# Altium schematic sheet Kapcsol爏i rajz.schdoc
size 319 x 215 mm
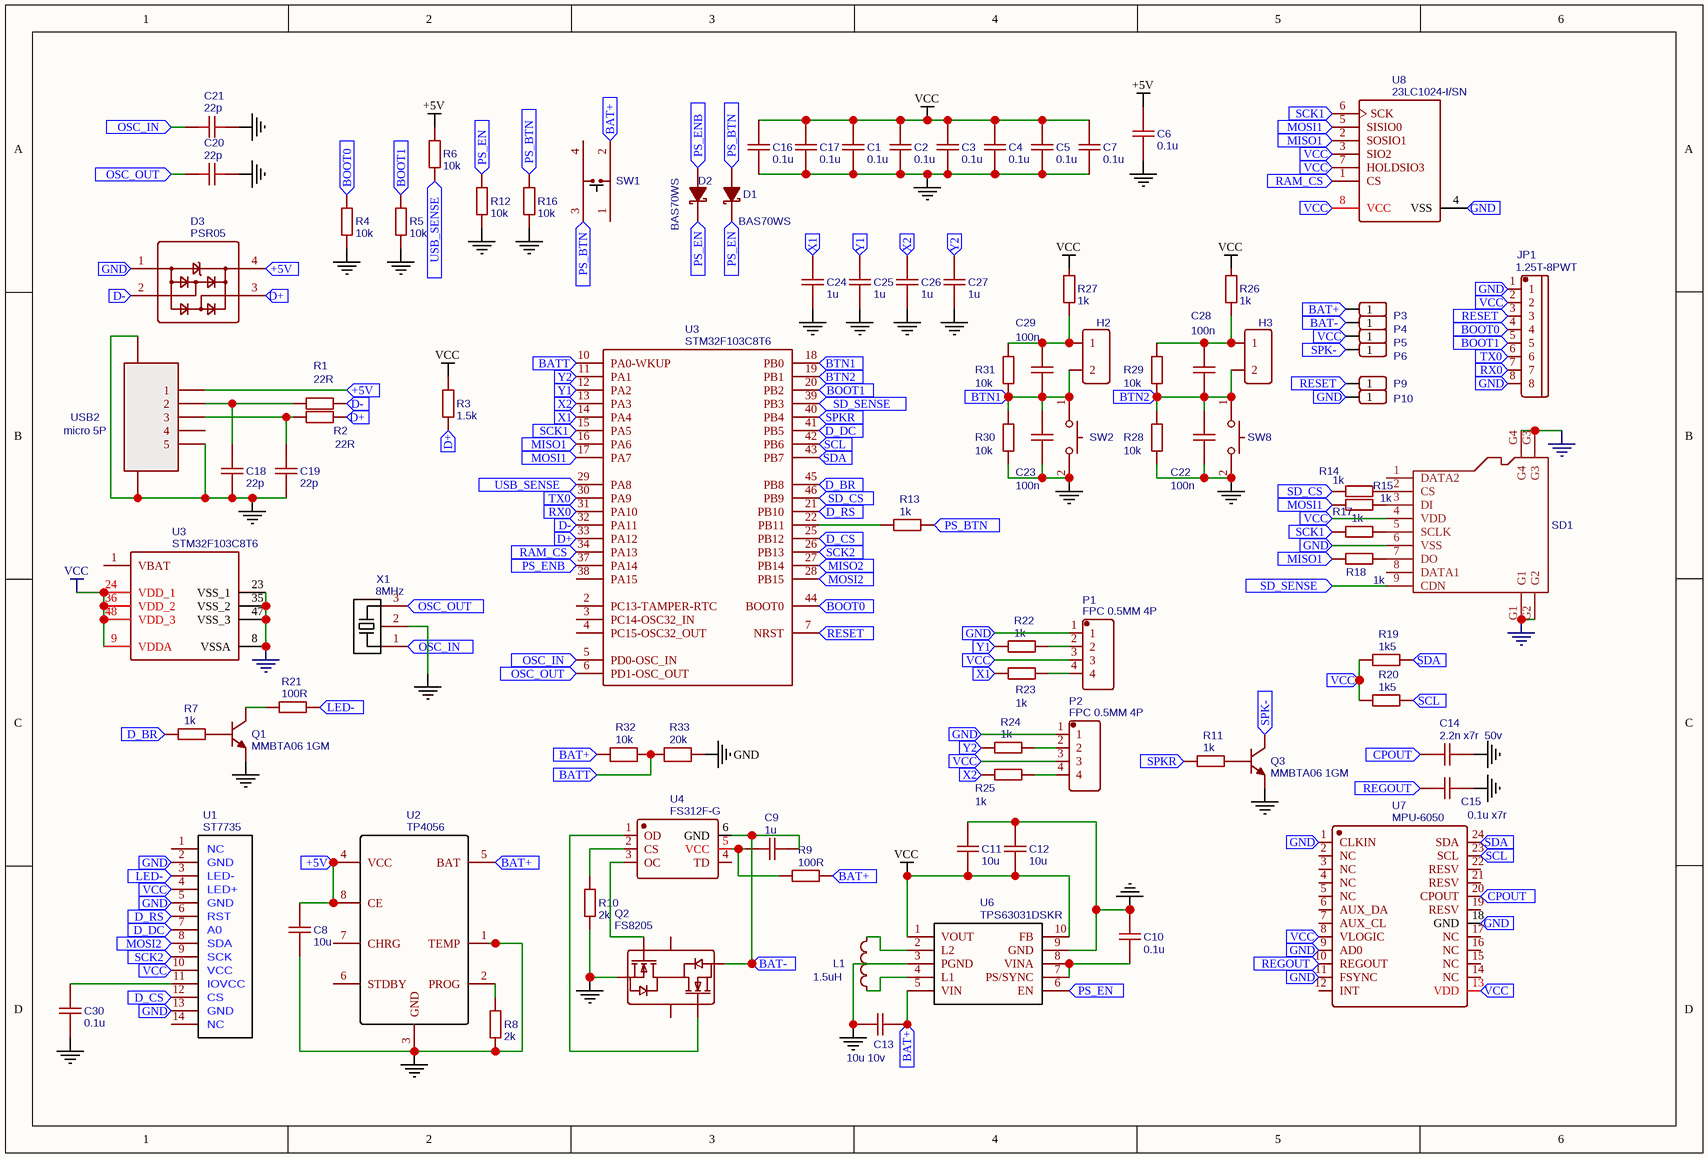
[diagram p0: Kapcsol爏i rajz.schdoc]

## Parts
(Parts that share a designator on the sheet are numbered #1, #2 ... from top to bottom, then left to right.)
C1  0.1u  [0805]
C2  0.1u  [0805]
C3  0.1u  [0805]
C4  0.1u  [0805]
C5  0.1u  [0805]
C6  0.1u  [0805]
C7  0.1u  [0805]
C8  10u  [0805]
C9  1u  [0805]
C10  0.1u  [0805]
C11  10u  [0805]
C12  10u  [0805]
C13  10u 10v  [0805]
C14  2.2n x7r  50v  [0805]
C15  0.1u x7r  [0805]
C16  0.1u  [0805]
C17  0.1u  [0805]
C18  22p  [0805]
C19  22p  [0805]
C20  22p  [0805]
C21  22p  [0805]
C22  100n  [0805]
C23  100n  [0805]
C24  1u  [0805]
C25  1u  [0805]
C26  1u  [0805]
C27  1u  [0805]
C28  100n  [0805]
C29  100n  [0805]
C30  0.1u  [0805]
D1  BAS70WS  [SOD-323]
D2  BAS70WS  [SOD-323]
D3  PSR05  [SOT-143]
H2  Header-Male-2.54_1x2  [HDR-2X1/2.54]  (value not drawn)
H3  Header-Male-2.54_1x2  [HDR-2X1/2.54]  (value not drawn)
JP1  1.25T-8PWT  [1.25T-8PWT]
L1  1.5uH  [3.0*3.0*1.5MM]
P1  FPC 0.5MM 4P  [FPC-0.5MM-LSSJ-H2.0-4P]
P2  FPC 0.5MM 4P  [FPC-0.5MM-LSSJ-H2.0-4P]
P3  Header-Male-2.54_1x1  [HDR-1X1/2.54]  (value not drawn)
P4  Header-Male-2.54_1x1  [HDR-1X1/2.54]  (value not drawn)
P5  Header-Male-2.54_1x1  [HDR-1X1/2.54]  (value not drawn)
P6  Header-Male-2.54_1x1  [HDR-1X1/2.54]  (value not drawn)
P9  Header-Male-2.54_1x1  [HDR-1X1/2.54]  (value not drawn)
P10  Header-Male-2.54_1x1  [HDR-1X1/2.54]  (value not drawn)
Q1  MMBTA06 1GM  [SOT-23(SOT-23-3)]
Q2  FS8205  [SOT-23-6]
Q3  MMBTA06 1GM  [SOT-23(SOT-23-3)]
R1  22R  [0805]
R2  22R  [0805]
R3  1.5k  [0805]
R4  10k  [0805]
R5  10k  [0805]
R6  10k  [0805]
R7  1k  [0805]
R8  2k  [0805]
R9  100R  [0805]
R10  2k  [0805]
R11  1k  [0805]
R12  10k  [0805]
R13  1k  [0805]
R14  1k  [0805]
R15  1k  [0805]
R16  10k  [0805]
R17  1k  [0805]
R18  1k  [0805]
R19  1k5  [0805]
R20  1k5  [0805]
R21  100R  [0805]
R22  1k  [0805]
R23  1k  [0805]
R24  1k  [0805]
R25  1k  [0805]
R26  1k  [0805]
R27  1k  [0805]
R28  10k  [0805]
R29  10k  [0805]
R30  10k  [0805]
R31  10k  [0805]
R32  10k  [0805]
R33  20k  [0805]
SD1  ST-TF-003A  [MICRO-SD9+4P-SMD-16.1X14.5X1.85MM]  (value not drawn)
SW1  SKSCLDE010  [SKSCLDE010]  (value not drawn)
SW2  SKSTAAE010  [SW-SMD-8.5X8.5X3.95]  (value not drawn)
SW8  SKSTAAE010  [SW-SMD-8.5X8.5X3.95]  (value not drawn)
U1  ST7735  [ST7735 14PIN SHORT OUTLINE]
U2  TP4056  [SOP-8_EP_150MIL]
U3#1  STM32F103C8T6  [LQFP-48_7X7X05P]
U3#2  STM32F103C8T6  [LQFP-48_7X7X05P]
U4  FS312F-G  [SOT23-6]
U6  TPS63031DSKR  [SON-10_3X3X05P]
U7  MPU-6050  [QFN-24_4X4X05P]
U8  23LC1024-I/SN  [SOP-8_150MIL]
USB2  micro 5P  [MICRO-USB-3]
X1  8MHz  [3213]

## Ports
+5V, BAT+, BAT-, BATT, BOOT0, BOOT1, BTN1, BTN2, CPOUT, D+, D-, D_BR, D_CS, D_DC, D_RS, GND, LED-, MISO1, MISO2, MOSI1, MOSI2, OSC_IN, OSC_OUT, PS_BTN, PS_EN, PS_ENB, RAM_CS, REGOUT, RESET, RX0, SCK1, SCK2, SCL, SD_CS, SD_SENSE, SDA, SPK-, SPKR, TX0, USB_SENSE, VCC, X1, X2, Y1, Y2

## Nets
+5V: C6.2 R6.2
GND: C1.1 C2.1 C3.1 C4.1 C5.1 C6.1 C7.1 C8.1 C10.1 C11.1 C12.1 C13.2 C14.2 C15.2 C16.1 C17.1 C18.1 C19.1 C20.1 C21.1 C22.1 C23.1 C24.1 C25.1 C26.1 C27.1 C30.2 Q1.2(E) Q2.1(S1) Q3.2(E) R4.1 R5.1 R8.1 R10.1 R12.1 R16.1 R28.1 R30.1 R33.2 SD1.G1 SD1.G2 SD1.G3 SD1.G4 SW2.2 SW8.2 U2.1(TEMP) U2.3(GND) U3#2.8(VSSA) U3#2.23(VSS_1) U3#2.35(VSS_2) U3#2.47(VSS_3) U6.3(PGND) U6.9(GND) USB2.0 USB2.5 X1.2
VCC: C1.2 C2.2 C3.2 C4.2 C5.2 C7.2 C11.2 C12.2 C16.2 C17.2 R3.1 U3#2.9(VDDA) U3#2.24(VDD_1) U3#2.36(VDD_2) U3#2.48(VDD_3) U6.1(VOUT) U6.10(FB)
+5V: C8.2 D3.4 U2.4(VCC) U2.8(CE) USB2.1 ; port +5V  [a separate net that carries the same name]
BAT+: C13.1 P3.1 R9.2 R32.1 SW1.2 U2.5(BAT) U6.5(VIN) ; port BAT+
BAT-: C9.1 P4.1 Q2.3(S2) U4.6(GND) ; port BAT-
BATT: R32.2 R33.1 U3#1.10(PA0-WKUP) ; port BATT
BOOT0: JP1.4 R4.2 U3#1.44(BOOT0) ; port BOOT0
BOOT1: JP1.5 R5.2 U3#1.20(PB2) ; port BOOT1
BTN1: C23.2 C29.1 H2.2 R30.2 R31.1 SW2.1 U3#1.18(PB0) ; port BTN1
BTN2: C22.2 C28.1 H3.2 R28.2 R29.1 SW8.1 U3#1.19(PB1) ; port BTN2
CPOUT: C14.1 U7.20(CPOUT) ; port CPOUT
D+: D3.3 R2.2 R3.2 U3#1.33(PA12) ; port D+
D-: D3.2 R1.2 U3#1.32(PA11) ; port D-
D_BR: R7.1 U3#1.45(PB8) ; port D_BR
D_CS: U1.12 U3#1.25(PB12) ; port D_CS
D_DC: U1.7 U3#1.41(PB5) ; port D_DC
D_RS: U1.6 U3#1.21(PB10) ; port D_RS
GND: D3.1 JP1.1 JP1.8 P1.1 P2.1 P10.1 SD1.6(VSS) U1.2 U1.5 U1.13 U7.1(CLKIN) U7.9(AD0) U7.11(FSYNC) U7.18(GND) U8.4(VSS) ; port GND  [a separate net that carries the same name]
LED-: R21.2 U1.3 ; port LED-
MISO1: R18.1 U3#1.16(PA6) U8.2(SOSIO1) ; port MISO1
MISO2: U3#1.27(PB14) ; port MISO2
MOSI1: R15.1 U3#1.17(PA7) U8.5(SISIO0) ; port MOSI1
MOSI2: U1.8 U3#1.28(PB15) ; port MOSI2
OSC_IN: C21.2 U3#1.5(PD0-OSC_IN) X1.1 ; port OSC_IN
OSC_OUT: C20.2 U3#1.6(PD1-OSC_OUT) X1.3 ; port OSC_OUT
PS_BTN: D1.1(A) R13.2 R16.2 SW1.3 ; port PS_BTN
PS_EN: D1.2(K) D2.2(K) R12.2 U6.6(EN) ; port PS_EN
PS_ENB: D2.1(A) U3#1.37(PA14) ; port PS_ENB
RAM_CS: U3#1.34(PA13) U8.1(CS) ; port RAM_CS
REGOUT: C15.1 U7.10(REGOUT) ; port REGOUT
RESET: JP1.3 P9.1 U3#1.7(NRST) ; port RESET
RX0: JP1.7 U3#1.31(PA10) ; port RX0
SCK1: R17.1 U3#1.15(PA5) U8.6(SCK) ; port SCK1
SCK2: U1.9 U3#1.26(PB13) ; port SCK2
SCL: R20.2 U3#1.42(PB6) U7.23(SCL) ; port SCL
SD_CS: R14.1 U3#1.46(PB9) ; port SD_CS
SD_SENSE: SD1.9(CDN) U3#1.39(PB3) ; port SD_SENSE
SDA: R19.2 U3#1.43(PB7) U7.24(SDA) ; port SDA
SPK-: P6.1 Q3.3(C) ; port SPK-
SPKR: R11.1 U3#1.40(PB4) ; port SPKR
TX0: JP1.6 U3#1.30(PA9) ; port TX0
USB_SENSE: R6.1 U3#1.29(PA8) ; port USB_SENSE
VCC: JP1.2 P1.3 P2.3 P5.1 R19.1 R20.1 SD1.4(VDD) U1.4 U1.10 U7.8(VLOGIC) U7.13(VDD) U8.3(SIO2) U8.7(HOLDSIO3) U8.8(VCC) ; port VCC  [a separate net that carries the same name]
X1: C24.2 R23.1 U3#1.14(PA4) ; port X1
X2: C26.2 R25.1 U3#1.13(PA3) ; port X2
Y1: C25.2 R22.1 U3#1.12(PA2) ; port Y1
Y2: C27.2 R24.1 U3#1.11(PA1) ; port Y2
NetC9_2: C9.2 R9.1 U4.5(VCC)
NetC10_2: C10.2 U6.7(PS/SYNC) U6.8(VINA)
NetC18_2: C18.2 R1.1 USB2.2
NetC19_2: C19.2 R2.1 USB2.3
NetC28_2: C28.2 H3.1 R26.2 R29.2
NetC29_2: C29.2 H2.1 R27.2 R31.2
NetC30_1: C30.1 U1.11
NetL1_1: L1.1 U6.4(L1)
NetL1_2: L1.2 U6.2(L2)
NetP1_2: P1.2 R22.2
NetP1_4: P1.4 R23.2
NetP2_2: P2.2 R24.2
NetP2_4: P2.4 R25.2
NetQ1_1: Q1.1(B) R7.2
NetQ1_3: Q1.3(C) R21.1
NetQ2_4: Q2.4(G2) U4.1(OD)
NetQ2_6: Q2.6(G1) U4.3(OC)
NetQ3_1: Q3.1(B) R11.2
NetR8_2: R8.2 U2.2(PROG)
NetR10_2: R10.2 U4.2(CS)
NetR13_1: R13.1 U3#1.22(PB11)
NetR14_2: R14.2 SD1.2(CS)
NetR15_2: R15.2 SD1.3(DI)
NetR17_2: R17.2 SD1.5(SCLK)
NetR18_2: R18.2 SD1.7(DO)

Not connected (* = marked no-connect by the designer): Q2 2(D12) 5(D12); R26 1; R27 1; SD1 1(DATA2) 8(DATA1); SW1 1 4; U1 1 14(1); U2 6(STDBY) 7(CHRG); U3#1 2(PC13-TAMPER-RTC) 3(PC14-OSC32_IN) 4(PC15-OSC32_OUT) 38(PA15); U3#2 1(VBAT); U4 4(TD); U7 2(NC) 3(NC) 4(NC) 5(NC) 6(AUX_DA) 7(AUX_CL) 12(INT) 14(NC) 15(NC) 16(NC) 17(NC) 19(RESV) 21(RESV) 22(RESV); USB2 4

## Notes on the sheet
- Labels drawn without touching a wire or pin: VCC

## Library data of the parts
C1-C7 C10 C16 C17 C30 = 0.1u: nameAlias: Value(F)
C8 C11 C12 = 10u: nameAlias: Value(F)
C9 C24-C27 = 1u: nameAlias: Value(F)
C13 = 10u 10v: nameAlias: Value(F)
C14 = 2.2n x7r  50v: nameAlias: Value(F)
C15 = 0.1u x7r: nameAlias: Value(F)
C18-C21 = 22p: nameAlias: Value(F)
C22 C23 C28 C29 = 100n: nameAlias: Value(F)
D1 D2 = BAS70WS: BOM_Manufacturer: CJ; Contributor: LCSC
D3 = PSR05: BOM_Manufacturer: Yenji; Contributor: LCSC
H2 H3 = Header-Male-2.54_1x2: BOM_Manufacturer: TE Connectivity; BOM_Manufacturer Part: 826629-2
JP1 = 1.25T-8PWT: BOM_Manufacturer: ReliaPro; Contributor: LCSC
L1 = 1.5uH: BOM_Manufacturer: TAIYO YUDEN; BOM_Manufacturer Part: NR3015T1R5N; nameAlias: Inductance; Contributor: LCSC
P1 P2 = FPC 0.5MM 4P: BOM_Manufacturer: ReliaPro; BOM_Manufacturer Part: FPC 0.5MM 4P Pull type H2.0mm Pick up; Contributor: LCSC
P3-P6 P9 P10 = Header-Male-2.54_1x1: BOM_Manufacturer: ReliaPro
Q1 Q3 = MMBTA06 1GM: BOM_Manufacturer: CJ; Contributor: LCSC
Q2 = FS8205: BOM_Manufacturer: FORTUNE; Contributor: LCSC
R1 R2 = 22R: nameAlias: Value(Ω)
R3 = 1.5k: nameAlias: Value(Ω)
R4-R6 R12 R16 R28-R32 = 10k: nameAlias: Value(Ω)
R7 R11 R13-R15 R17 R18 R22-R27 = 1k: nameAlias: Value(Ω)
R8 R10 = 2k: nameAlias: Value(Ω)
R9 R21 = 100R: nameAlias: Value(Ω)
R19 R20 = 1k5: nameAlias: Value(Ω)
R33 = 20k: nameAlias: Value(Ω)
SD1 = ST-TF-003A: description: Micro SD Card Socket
SW1 = SKSCLDE010: BOM_Manufacturer: ALPS; Contributor: LCSC
SW2 SW8 = SKSTAAE010: BOM_Manufacturer: ALPS Electric; Contributor: LCSC
U1 = ST7735: Contributor: sergey.drob
U2 = TP4056: BOM_Manufacturer: TOPPOWER; Contributor: LCSC
U3#1 = STM32F103C8T6: BOM_Manufacturer: ST; subpart_no: 1; tags: STM32
U3#2 = STM32F103C8T6: BOM_Manufacturer: ST; subpart_no: 2; tags: STM32
U4 = FS312F-G: BOM_Manufacturer: FORTUNE; Contributor: LCSC
U6 = TPS63031DSKR: BOM_Manufacturer: TI; Contributor: LCSC
U7 = MPU-6050: BOM_Manufacturer: InvenSense; sourceId: 1T5FDZYC8; Contributor: LCSC
U8 = 23LC1024-I/SN: BOM_Manufacturer: MICROCHIP; Contributor: LCSC
USB2 = micro 5P: BOM_Manufacturer: ValuePro; BOM_Manufacturer Part: micro 5PBroken plate1.274 Pins
X1 = 8MHz: BOM_Manufacturer: MuRata; BOM_Manufacturer Part: CSTCE8M00G15C99-R0; nameAlias: Frequency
